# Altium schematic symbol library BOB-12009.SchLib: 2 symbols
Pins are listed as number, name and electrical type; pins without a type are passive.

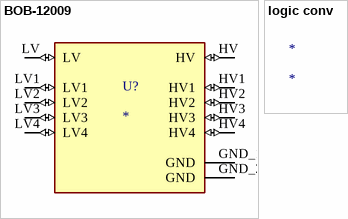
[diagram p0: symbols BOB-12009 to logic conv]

## BOB-12009
designator U?
BSS138 - Logic-Level Translator Interface Evaluation Board; MF: SparkFun; MP: BOB-12009
footprint CONV_BOB-12009
pins: GND_1 GND (power), GND_2 GND (power), HV (io), HV1 (io), HV2 (io), HV3 (io), HV4 (io), LV (io), LV1 (io), LV2 (io), LV3 (io), LV4 (io)

## logic conv
designator *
